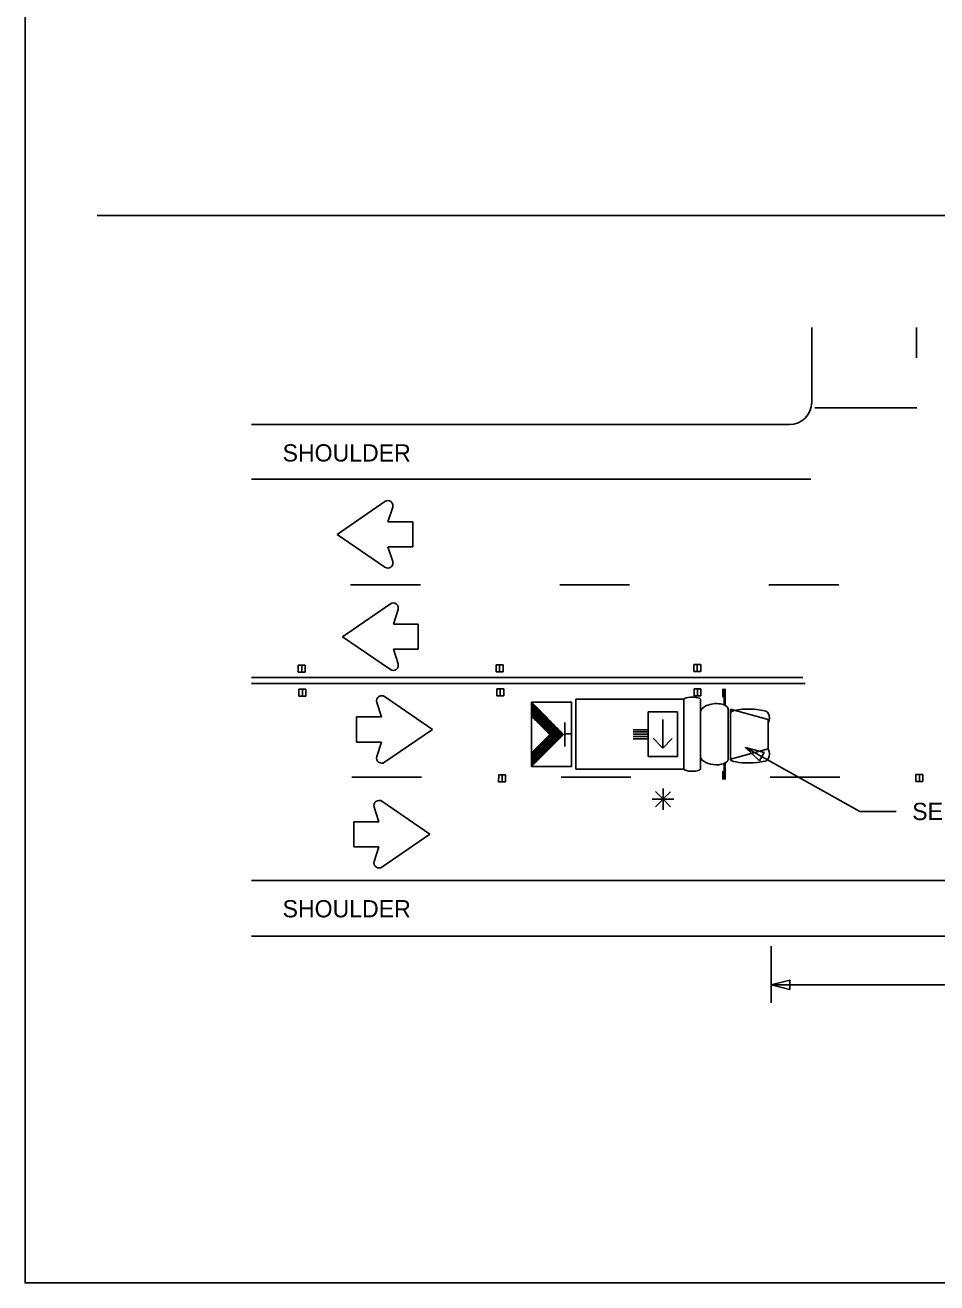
# Model space of a CAD drawing. Extents: x 1374027 to 1374537, y 380415 to 381405.
# Drawn here: x 1374027.08 to 1374058.79, y 381295.17 to 381338.93 of the extents above; entities that cross this region are included whole.
import ezdxf

# ---------------------------------------------------------------- set-up
doc = ezdxf.new("R2010")
doc.units = 0
for name, color, linetype in [('DSN_DRFT_Junk-No-Plot', 7, 'Continuous'), ('Level 1', 7, 'Continuous'), ('Working Level 1', 7, 'Continuous')]:
    doc.layers.add(name, color=color, linetype=linetype)

msp = doc.modelspace()

# ---------------------------------------------------------------- linework, layer by layer
at = {"layer": 'DSN_DRFT_Junk-No-Plot'}
for points in [[(1374027.083, 381405.174), (1374197.083, 381405.174), (1374197.083, 381295.174), (1374027.083, 381295.174)], [(1374027.083, 381405.174), (1374027.083, 381295.174), (1374197.083, 381295.174), (1374197.083, 381405.174)]]:
    msp.add_lwpolyline(points, close=True, dxfattribs=at)
at = {"layer": 'Level 1'}
msp.add_lwpolyline([(1374052.135, 381313.799), (1374056.119, 381311.569), (1374057.373, 381311.569)], dxfattribs=at)
at = {"layer": 'Working Level 1'}
for p, q in [((1374029.583, 381332.308), (1374114.922, 381332.308)), ((1374054.44, 381325.811), (1374054.44, 381328.41)), ((1374054.547, 381325.624), (1374058.093, 381325.624)), ((1374034.95, 381325.035), (1374053.664, 381325.035)), ((1374034.95, 381323.14), (1374054.407, 381323.14)), ((1374037.931, 381321.215), (1374039.598, 381322.359)), ((1374039.703, 381321.651), (1374039.866, 381322.159)), ((1374040.571, 381321.651), (1374039.703, 381321.651)), ((1374040.571, 381321.651), (1374040.571, 381320.778)), ((1374037.931, 381321.215), (1374039.598, 381320.071)), ((1374040.571, 381320.778), (1374039.703, 381320.778)), ((1374039.703, 381320.778), (1374039.866, 381320.271)), ((1374038.118, 381317.657), (1374039.785, 381318.8)), ((1374039.89, 381318.093), (1374040.053, 381318.601)), ((1374040.758, 381318.093), (1374039.89, 381318.093)), ((1374040.758, 381318.093), (1374040.758, 381317.22)), ((1374038.118, 381317.657), (1374039.785, 381316.513)), ((1374040.758, 381317.22), (1374039.89, 381317.22)), ((1374039.89, 381317.22), (1374040.053, 381316.713)), ((1374036.827, 381316.668), (1374036.584, 381316.668)), ((1374036.584, 381316.668), (1374036.584, 381316.425)), ((1374036.706, 381316.668), (1374036.705, 381316.425)), ((1374036.827, 381316.425), (1374036.827, 381316.668)), ((1374043.465, 381316.679), (1374043.464, 381316.436)), ((1374043.707, 381316.679), (1374043.465, 381316.679)), ((1374043.587, 381316.679), (1374043.586, 381316.436)), ((1374043.707, 381316.436), (1374043.707, 381316.679)), ((1374050.582, 381316.691), (1374050.339, 381316.691)), ((1374050.339, 381316.691), (1374050.339, 381316.448)), ((1374050.461, 381316.691), (1374050.461, 381316.448)), ((1374050.582, 381316.448), (1374050.582, 381316.691)), ((1374034.95, 381316.239), (1374054.13, 381316.239)), ((1374036.584, 381316.425), (1374036.827, 381316.425)), ((1374043.464, 381316.436), (1374043.707, 381316.436)), ((1374050.339, 381316.448), (1374050.582, 381316.448)), ((1374034.95, 381316.027), (1374054.21, 381316.027)), ((1374036.605, 381315.832), (1374036.604, 381315.589)), ((1374036.847, 381315.832), (1374036.605, 381315.832)), ((1374036.726, 381315.832), (1374036.726, 381315.589)), ((1374036.847, 381315.589), (1374036.847, 381315.832)), ((1374043.728, 381315.843), (1374043.485, 381315.843)), ((1374043.485, 381315.843), (1374043.485, 381315.6)), ((1374043.607, 381315.843), (1374043.606, 381315.6)), ((1374043.728, 381315.6), (1374043.728, 381315.843)), ((1374050.59, 381315.843), (1374050.347, 381315.843)), ((1374050.347, 381315.843), (1374050.347, 381315.6)), ((1374050.469, 381315.843), (1374050.468, 381315.6)), ((1374050.59, 381315.6), (1374050.59, 381315.843)), ((1374051.347, 381315.549), (1374051.347, 381315.846)), ((1374051.394, 381315.264), (1374051.394, 381315.846)), ((1374051.434, 381315.264), (1374051.434, 381315.846)), ((1374036.604, 381315.589), (1374036.847, 381315.589)), ((1374039.478, 381314.865), (1374039.315, 381315.372)), ((1374041.251, 381314.429), (1374039.584, 381315.572)), ((1374043.485, 381315.6), (1374043.728, 381315.6)), ((1374044.694, 381315.373), (1374045.812, 381314.256)), ((1374046.242, 381315.477), (1374049.996, 381315.477)), ((1374046.242, 381313.051), (1374046.242, 381315.477)), ((1374049.996, 381314.264), (1374049.996, 381315.477)), ((1374050.347, 381315.6), (1374050.59, 381315.6)), ((1374050.572, 381314.264), (1374050.572, 381315.477)), ((1374038.611, 381313.992), (1374038.611, 381314.865)), ((1374038.611, 381314.865), (1374039.478, 381314.865)), ((1374044.694, 381314.888), (1374045.335, 381314.249)), ((1374049.776, 381315.04), (1374048.75, 381315.04)), ((1374048.75, 381313.488), (1374048.75, 381315.04)), ((1374049.776, 381315.04), (1374049.776, 381313.488)), ((1374051.535, 381314.264), (1374051.535, 381315.138)), ((1374051.615, 381315.138), (1374052.928, 381314.779)), ((1374051.615, 381314.264), (1374051.615, 381315.138)), ((1374041.251, 381314.429), (1374039.584, 381313.285)), ((1374045.85, 381313.835), (1374045.85, 381314.676)), ((1374048.75, 381314.419), (1374048.227, 381314.419)), ((1374049.263, 381314.777), (1374049.263, 381313.783)), ((1374052.928, 381314.264), (1374052.928, 381314.779)), ((1374038.611, 381313.992), (1374039.478, 381313.992)), ((1374039.478, 381313.992), (1374039.315, 381313.485)), ((1374044.694, 381313.61), (1374045.335, 381314.249)), ((1374044.7, 381313.143), (1374045.812, 381314.256)), ((1374046.083, 381314.276), (1374045.843, 381314.276)), ((1374048.75, 381314.341), (1374048.227, 381314.341)), ((1374048.75, 381314.264), (1374048.227, 381314.264)), ((1374048.75, 381314.186), (1374048.227, 381314.186)), ((1374048.75, 381314.108), (1374048.227, 381314.108)), ((1374049.263, 381313.783), (1374048.925, 381314.121)), ((1374049.263, 381313.783), (1374049.592, 381314.113)), ((1374049.996, 381314.264), (1374049.996, 381313.052)), ((1374050.572, 381314.264), (1374050.572, 381313.052)), ((1374051.535, 381314.264), (1374051.535, 381313.391)), ((1374051.615, 381314.264), (1374051.615, 381313.391)), ((1374052.928, 381314.264), (1374052.928, 381313.749)), ((1374051.615, 381313.391), (1374052.928, 381313.749)), ((1374049.776, 381313.488), (1374048.75, 381313.488)), ((1374051.394, 381313.264), (1374051.394, 381312.682)), ((1374051.434, 381313.264), (1374051.434, 381312.682)), ((1374043.553, 381312.853), (1374043.552, 381312.61)), ((1374043.795, 381312.853), (1374043.553, 381312.853)), ((1374043.674, 381312.853), (1374043.674, 381312.61)), ((1374043.795, 381312.61), (1374043.795, 381312.853)), ((1374046.242, 381313.052), (1374049.996, 381313.052)), ((1374051.347, 381312.979), (1374051.347, 381312.682)), ((1374058.311, 381312.864), (1374058.068, 381312.864)), ((1374058.068, 381312.864), (1374058.068, 381312.621)), ((1374058.19, 381312.864), (1374058.189, 381312.621)), ((1374058.311, 381312.621), (1374058.311, 381312.864)), ((1374043.552, 381312.61), (1374043.795, 381312.61)), ((1374049.269, 381312.003), (1374049.003, 381312.269)), ((1374049.263, 381311.998), (1374049.529, 381312.264)), ((1374049.269, 381312.003), (1374049.269, 381312.38)), ((1374058.068, 381312.621), (1374058.311, 381312.621)), ((1374041.158, 381310.784), (1374039.491, 381311.928)), ((1374049.269, 381312.003), (1374048.893, 381312.003)), ((1374049.269, 381312.003), (1374049.003, 381311.737)), ((1374049.269, 381312.003), (1374049.535, 381311.737)), ((1374049.269, 381312.003), (1374049.269, 381311.627)), ((1374049.269, 381312.003), (1374049.645, 381312.003)), ((1374039.386, 381311.22), (1374039.223, 381311.728)), ((1374038.518, 381310.347), (1374038.518, 381311.22)), ((1374038.518, 381311.22), (1374039.386, 381311.22)), ((1374041.158, 381310.784), (1374039.491, 381309.64)), ((1374038.518, 381310.347), (1374039.386, 381310.347)), ((1374039.386, 381310.347), (1374039.223, 381309.84)), ((1374034.95, 381309.174), (1374114.956, 381309.174)), ((1374034.95, 381307.236), (1374114.956, 381307.236)), ((1374053.027, 381306.888), (1374053.027, 381304.922)), ((1374053.027, 381305.548), (1374084.724, 381305.548)), ((1374053.027, 381305.548), (1374053.57, 381305.548))]:
    msp.add_line(p, q, dxfattribs=at)
for points in [[(1374058.089, 381328.41), (1374058.089, 381327.363)], [(1374038.404, 381319.466), (1374040.829, 381319.466)], [(1374045.679, 381319.466), (1374048.105, 381319.466)], [(1374052.955, 381319.466), (1374055.38, 381319.466)], [(1374044.694, 381315.32), (1374045.284, 381314.299)], [(1374044.744, 381315.324), (1374045.525, 381313.97)], [(1374044.694, 381315.233), (1374045.167, 381314.413)], [(1374044.694, 381315.145), (1374045.05, 381314.527)], [(1374044.694, 381315.057), (1374044.933, 381314.642)], [(1374044.694, 381314.969), (1374044.817, 381314.757)], [(1374044.694, 381314.881), (1374044.7, 381314.871)], [(1374044.863, 381315.204), (1374045.557, 381314.002)], [(1374044.983, 381315.084), (1374045.59, 381314.034)], [(1374045.103, 381314.964), (1374045.622, 381314.066)], [(1374045.223, 381314.844), (1374045.654, 381314.098)], [(1374045.343, 381314.724), (1374045.687, 381314.128)], [(1374045.463, 381314.605), (1374045.72, 381314.159)], [(1374045.583, 381314.486), (1374045.75, 381314.196)], [(1374045.031, 381313.947), (1374045.203, 381313.649)], [(1374045.062, 381313.978), (1374045.235, 381313.681)], [(1374045.095, 381314.011), (1374045.268, 381313.713)], [(1374045.127, 381314.043), (1374045.299, 381313.746)], [(1374045.159, 381314.074), (1374045.332, 381313.777)], [(1374045.192, 381314.107), (1374045.364, 381313.809)], [(1374045.224, 381314.139), (1374045.396, 381313.842)], [(1374045.256, 381314.171), (1374045.428, 381313.873)], [(1374045.288, 381314.204), (1374045.461, 381313.906)], [(1374045.321, 381314.236), (1374045.493, 381313.938)], [(1374045.693, 381314.377), (1374045.78, 381314.227)], [(1374044.694, 381313.563), (1374044.848, 381313.296)], [(1374044.709, 381313.625), (1374044.88, 381313.329)], [(1374044.741, 381313.657), (1374044.913, 381313.36)], [(1374044.773, 381313.689), (1374044.944, 381313.393)], [(1374044.806, 381313.722), (1374044.977, 381313.424)], [(1374044.837, 381313.753), (1374045.009, 381313.457)], [(1374044.87, 381313.785), (1374045.041, 381313.489)], [(1374044.902, 381313.817), (1374045.074, 381313.521)], [(1374044.934, 381313.85), (1374045.106, 381313.553)], [(1374044.967, 381313.882), (1374045.138, 381313.585)], [(1374044.999, 381313.914), (1374045.171, 381313.617)], [(1374044.694, 381313.474), (1374044.816, 381313.264)], [(1374044.694, 381313.387), (1374044.784, 381313.232)], [(1374044.694, 381313.298), (1374044.752, 381313.2)], [(1374044.694, 381313.211), (1374044.719, 381313.168)], [(1374038.448, 381312.768), (1374040.873, 381312.768)], [(1374045.723, 381312.768), (1374048.149, 381312.768)], [(1374052.999, 381312.768), (1374055.424, 381312.768)]]:
    msp.add_lwpolyline(points, dxfattribs=at)
for points in [[(1374044.694, 381315.373), (1374044.694, 381313.143), (1374046.088, 381313.143), (1374046.088, 381315.373)], [(1374052.623, 381313.339), (1374052.135, 381313.799), (1374052.782, 381313.623)], [(1374053.677, 381305.385), (1374053.027, 381305.548), (1374053.677, 381305.71)]]:
    msp.add_lwpolyline(points, close=True, dxfattribs=at)
for centre, radius, start, end in [((1374053.664, 381325.811), 0.776, 270, 360), ((1374039.698, 381322.213), 0.177, 342.1824, 124.4455), ((1374039.698, 381320.217), 0.177, 235.5545, 17.8176), ((1374039.885, 381318.655), 0.177, 342.1824, 124.4455), ((1374039.885, 381316.659), 0.177, 235.5545, 17.8176), ((1374039.484, 381315.426), 0.177, 55.5545, 197.8176), ((1374052.607, 381314.823), 0.364, 331.8801, 28.1199), ((1374052.607, 381313.578), 0.364, 331.8801, 28.1199), ((1374039.484, 381313.431), 0.177, 162.1824, 304.4455), ((1374039.391, 381311.782), 0.177, 55.5545, 197.8176), ((1374039.391, 381309.786), 0.177, 162.1824, 304.4455)]:
    msp.add_arc(centre, radius, start, end, dxfattribs=at)
for centre, major_axis, ratio, start_param, end_param in [((1374050.284, 381315.477), (0.288, 0), 0.269913, 0, 3.141593), ((1374051.053, 381315.078), (0.482, 0.06), 0.503092, 0, 3.141593), ((1374052.272, 381315.003), (0.656, -0.008), 0.2034, 0, 3.141593), ((1374051.053, 381313.45), (0.482, -0.06), 0.503092, 3.141593, 6.283185), ((1374052.272, 381313.398), (0.656, 0.008), 0.2034, 3.141593, 6.283185), ((1374050.284, 381313.052), (0.288, 0), 0.269913, 3.141593, 6.283185)]:
    msp.add_ellipse(centre, major_axis=major_axis, ratio=ratio, start_param=start_param, end_param=end_param, dxfattribs=at)

# ---------------------------------------------------------------- texts
for p in [(1374036.037, 381323.752), (1374036.037, 381307.891)]:
    msp.add_text('SHOULDER', height=0.6, rotation=0, dxfattribs=at).set_placement(p)
msp.add_text('SEE TRAIL/SHADOW VEHICLE A', height=0.6, dxfattribs=at).set_placement((1374057.937, 381311.276))

doc.saveas('drawing.dxf')
